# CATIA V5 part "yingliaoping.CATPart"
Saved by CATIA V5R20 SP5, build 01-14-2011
Part number: yingliaoping
Material "Sunset"
Material "Summer sky"
Bounding box of the stored display mesh (mm): x -25 to 26, y -25 to 25, z 0 to 110
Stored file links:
  E:\180222112\yingliaoping.CATPart
  C:\Program Files\Dassault Systemes\B20\intel_a\startup\materials\Catalog.CATMaterial
  C:\Program Files\Dassault Systemes\B20\intel_a\startup\materials\fence_3.jpg
  C:\Program Files\Dassault Systemes\B20\intel_a\startup\materials\canvas.jpg
  C:\Program Files\Dassault Systemes\B20\intel_a\startup\materials\brown_fiber.jpg
  C:\Program Files\Dassault Systemes\B20\intel_a\startup\materials\marble_paving.jpg
  C:\Program Files\Dassault Systemes\B20\intel_a\startup\materials\old_tile.jpg
  C:\Program Files\Dassault Systemes\B20\intel_a\startup\materials\wall_of_bricks.jpg
  C:\Program Files\Dassault Systemes\B20\intel_a\startup\materials\roughcast.jpg
  C:\Program Files\Dassault Systemes\B20\intel_a\startup\materials\grid.png
  C:\Program Files\Dassault Systemes\B20\intel_a\startup\materials\blue_env_512x512.jpg
  C:\Program Files\Dassault Systemes\B20\intel_a\startup\materials\DS_star.jpg
  C:\Program Files\Dassault Systemes\B20\intel_a\startup\materials\chessboard.jpg
  C:\Program Files\Dassault Systemes\B20\intel_a\startup\materials\sunset.jpg
  C:\Program Files\Dassault Systemes\B20\intel_a\startup\materials\summer_sky.jpg
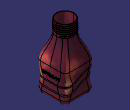
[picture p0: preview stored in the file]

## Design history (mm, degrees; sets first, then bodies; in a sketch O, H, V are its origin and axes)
Set1
  Sketch1 on xy-plane, origin (0, 0, 0), H (1, 0, 0), V (0, 1, 0)
    line L1 (25, 25) -> (25, -25)
    line L2 (25, -25) -> (-25, -25)
    line L3 (-25, -25) -> (-25, 25)
    line L4 (-25, 25) -> (25, 25)
    length L4 = 50
    length L1 = 50
    vertical: L1 V, L3 V
    horizontal: L2 H, L4 H
    equidistance: L1 L3 O, L2 L4 O
  Sketch2 on face of Pad1 from Sketch1.L2, origin (0, -25, 0), H (1, 0, 0), V (0, 0, 1)
    spline S1 through (-40.13, 17.5064) (-4.5865, 26.557) (17.4166, 15.9725) (37.4194, 24.256)
  Extrude1: Element1 Sketch2, Lim1 60, Lim2 60
  MultiSel1: CommonCtxFeats ({extract ExtractElem face of Pad1 from Sketch1.L2}; {extract ExtractElem face of Fillet1}; {extract ExtractElem face of Pad1 from Sketch1.L1}; {extract ExtractElem face of Fillet1}; {extract ExtractElem face of Pad1 from Sketch1.L4}; {extract ExtractElem face of Fillet1}; {extract ExtractElem face of Pad1 from Sketch1.L3}; {extract ExtractElem face of Fillet1}; {join Elements ({intersect ToIntersect1 {extract ExtractElem face of Pad1 from Sketch1.L2}, ToIntersect2 Extrude1}; {intersect ToIntersect1 {extract ExtractElem face of Fillet1}, ToIntersect2 Extrude1}; {intersect ToIntersect1 {extract ExtractElem face of Pad1 from Sketch1.L1}, ToIntersect2 Extrude1}; {intersect ToIntersect1 {extract ExtractElem face of Pad1 from Sketch1.L4}, ToIntersect2 Extrude1}; {intersect ToIntersect1 {extract ExtractElem face of Fillet1}, ToIntersect2 Extrude1}; {intersect ToIntersect1 {extract ExtractElem face of Fillet1}, ToIntersect2 Extrude1}; {intersect ToIntersect1 {extract ExtractElem face of Pad1 from Sketch1.L3}, ToIntersect2 Extrude1}; {intersect ToIntersect1 {extract ExtractElem face of Fillet1}, ToIntersect2 Extrude1})})
  Sketch3 on face of Pad1 from Sketch1.L2, origin (0, -25, 0), H (1, 0, 0), V (0, 0, 1)
    spline S1 through (-31.3579, 34.1236) (-14.7105, 40.4955) (13.6792, 27.8998) (28.8403, 27.8998)
  Extrude2: Element1 Sketch3, Lim1 60, Lim2 60
  MultiSel2: CommonCtxFeats ({extract ExtractElem face of Fillet1}; {extract ExtractElem face of Pad1 from Sketch1.L1}; {extract ExtractElem face of Fillet1}; {extract ExtractElem face of Pad1 from Sketch1.L4}; {extract ExtractElem face of Fillet1}; {extract ExtractElem face of Pad1 from Sketch1.L3}; {extract ExtractElem face of Fillet1}; {extract ExtractElem face of Pad1 from Sketch1.L2}; {join Elements ({intersect ToIntersect1 {extract ExtractElem face of Fillet1}, ToIntersect2 Extrude2}; {intersect ToIntersect1 {extract ExtractElem face of Pad1 from Sketch1.L1}, ToIntersect2 Extrude2}; {intersect ToIntersect1 {extract ExtractElem face of Fillet1}, ToIntersect2 Extrude2}; {intersect ToIntersect1 {extract ExtractElem face of Pad1 from Sketch1.L4}, ToIntersect2 Extrude2}; {intersect ToIntersect1 {extract ExtractElem face of Fillet1}, ToIntersect2 Extrude2}; {intersect ToIntersect1 {extract ExtractElem face of Pad1 from Sketch1.L3}, ToIntersect2 Extrude2}; {intersect ToIntersect1 {extract ExtractElem face of Fillet1}, ToIntersect2 Extrude2}; {intersect ToIntersect1 {extract ExtractElem face of Pad1 from Sketch1.L2}, ToIntersect2 Extrude2})})
  Plane1: type Normal, Curve {intersect ToIntersect1 {extract ExtractElem face of Pad1 from Sketch1.L4}, ToIntersect2 Extrude2}, RefPoint vertex of MultiSel2
  Sketch4 on Plane1, origin (-17.4023, 0, 0.6186), H (0, 1, 0), V (0.0355, 0, 0.9994)
    circle A1 centre (25.3111, 40.1619) radius 1
    radius A1 = 1
  Plane2: type Normal, Curve {intersect ToIntersect1 {join Elements ({intersect ToIntersect2 Extrude1}; {intersect ToIntersect2 Extrude1}; {intersect ToIntersect2 Extrude1}; {intersect ToIntersect2 Extrude1}; {intersect ToIntersect2 Extrude1}; {intersect ToIntersect2 Extrude1}; {intersect ToIntersect2 Extrude1}; {intersect ToIntersect2 Extrude1})}, ToIntersect2 Extrude1}, RefPoint vertex of MultiSel1
  Sketch5 on Plane2, origin (-17.7485, 0, 3.598), H (0, -1, 0), V (0.1987, 0, 0.9801)
    circle A1 centre (-24.9885, 25.9108) radius 1
    radius A1 = 1
Body1 (main body), material "Sunset"
  Pad1: profile Sketch1, direction (0, 0, 1), length 50
  Fillet1: on edge [face of Pad1 from Sketch1.L4 | face of Pad1 from Sketch1.L1]; edge [face of Pad1 from Sketch1.L3 | face of Pad1 from Sketch1.L4]; edge [face of Pad1 from Sketch1.L1 | face of Pad1 from Sketch1.L2]; edge [face of Pad1 from Sketch1.L2 | face of Pad1 from Sketch1.L3]
  Fillet2: radius 8, on edge [start face of Pad1 | face of Pad1 from Sketch1.L1]
  Plane3: type Offset, RefPlane end face of Pad1, Offset 40, reversed
  Sketch6 on Plane3, origin (0, 0, 90), H (1, 0, 0), V (0, -1, 0)
    circle A1 centre (0, 0) radius 15
    radius A1 = 15
  Pad2: profile Sketch6, direction (0, 0, 1), length 20
  Sketch7 on end face of Pad1, origin (0, 0, 50), H (1, 0, 0), V (0, 1, 0)
    point P1 (25, 0)
    distance P1 O = 25
    coincidence: P1 H
  Sketch8 on start face of Pad2, origin (0, 0, 90), H (1, 0, 0), V (0, -1, 0)
    point P1 (15, 0)
    distance P1 O = 15
    coincidence: P1 H
  Loft1: solid, Sections ({boundary Boundary {extract ExtractElem end face of Pad1}}; {boundary Boundary {extract ExtractElem start face of Pad2}}), StartFace end face of Pad1, EndFace start face of Pad2
  Slot1: profile Sketch4, centre curve {intersect ToIntersect1 {join}, ToIntersect2 Extrude2}
  Slot2: profile Sketch5, centre curve {intersect ToIntersect1 {join}, ToIntersect2 Extrude1}
  Shell1: ExtOffset 0, Face end face of Pad2, IntOffset 1
  Plane4: type Offset, RefPlane {extract ExtractElem start face of Pad2}, Offset 2
  Sketch9 on Plane4, origin (0, 0, 92), H (1, 0, 0), V (0, 1, 0)
    point P1 (15, 0)
    distance P1 O = 15
    coincidence: P1 H
  Helix1: Direction Z axis, RefPoint Sketch9, Pitch 3, Height 16, TaperAngle 0
  Line1: type PtDir, RefPoint Sketch9, Direction (1, 0, 0), Start 0, End 5
  Line2: type PtDir, RefPoint vertex of Helix1, Direction (0, 1, 0), Start 0, End 5
  Point1: type OnCurve, Support Helix1, Length 6.943
  Point2: type OnCurve, Support Helix1, RefPoint vertex of Helix1, Length -5.555
  Connect1: Curve1 Line2, Point1 vertex of Line2, Tension1 1, Curve2 Helix1, Point2 Point2, Tension2 1
  Connect2: Curve1 Line1, Point1 vertex of Line1, Tension1 1, Curve2 Connect1, Point2 Point1, Tension2 1
  Plane5: type Normal, Curve Connect2, RefPoint vertex of Connect2
  Sketch10 on Plane5, origin (10, 0, 0), H (0, 1, 0), V (0, 0, 1)
    circle A1 centre (0, 92.0244) radius 0.5
    point P1 (0, 92.0244)
    radius A1 = 0.5
    coincidence: P1 V
  Rib1: profile Sketch10, centre curve Connect2, thin wall 10
  Body2
    Sketch11 on Plane4, origin (0, 0, 92), H (1, 0, 0), V (0, 1, 0)
      circle A1 centre (0, 0) radius 14
      radius A1 = 14
    Pad3: profile Sketch11, direction (0, 0, -1), length 20, mirrored extent
  Remove1: tool Body2
Body3, material "Summer sky"
  Sketch12 on face of Pad1 from Sketch1.L1, origin (25, 0, 0), H (0, 1, 0), V (0, 0, 1)
    polyline C1
    polyline C2
    polyline C3
    polyline C4
    polyline C5
    polyline C6
    polyline C7
    polyline C8
    polyline C9
    polyline C10
    polyline C11
  Pocket1: profile Sketch12, direction (1, 0, 0), length 1
  Sketch13 on Plane4, origin (0, 0, 92), H (1, 0, 0), V (0, 1, 0)
    circle A1 centre (0, 0) radius 15
    radius A1 = 15
  Pad4: profile Sketch13, direction (0, 0, 1), length 20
